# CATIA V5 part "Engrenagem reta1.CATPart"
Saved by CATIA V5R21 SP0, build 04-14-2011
Part number: Engrenagem reta1
Definition: Engrenagem reta1
Nomenclature: Engrenagem reta12
Source: Unknown
Bounding box of the stored display mesh (mm): x -1.394 to 1.394, y -1.399 to 1.399, z 0 to 1.25
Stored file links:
  C:\Users\beatr\OneDrive\Documents\UNB\2026_1\Pi1\Componentes eletronicos\Engrenagem reta1.CATPart
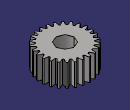
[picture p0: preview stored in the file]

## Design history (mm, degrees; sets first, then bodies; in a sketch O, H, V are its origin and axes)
Body1 "Solid1" (main body)
  Solid1: solid without history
